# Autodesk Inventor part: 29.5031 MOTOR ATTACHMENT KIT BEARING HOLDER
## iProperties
Created: 2006-12
Part Number: 29.5031 MOTOR ATTACHMENT KIT BEARING HOLDER
Material: Steel
Document SubType Name: Modeling
Designer: Andy Moles
Density: 7.85 g/cm^3
Author: Andy Moles
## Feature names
1. Extrusion1
